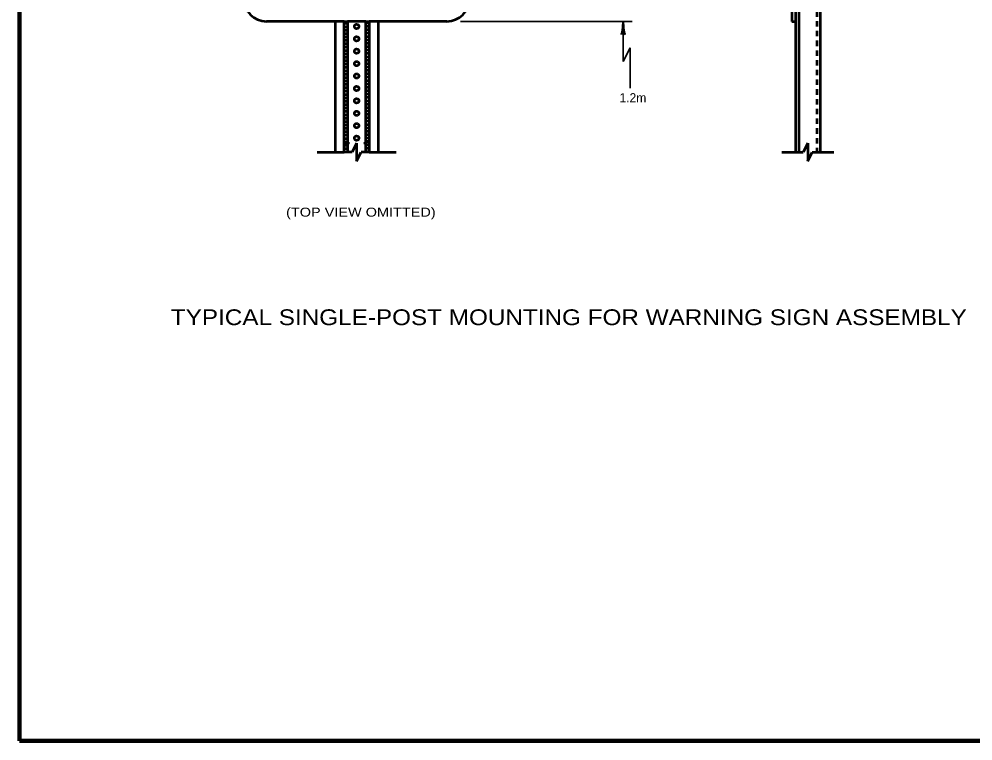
# Model space of a CAD drawing. Extents: x -87 to 768, y -466 to 78.
# Drawn here: x -29.9 to 223.8, y -454.3 to -262.3 of the extents above; entities that cross this region are included whole.
import ezdxf
from ezdxf.enums import TextEntityAlignment as Align

# ---------------------------------------------------------------- set-up
doc = ezdxf.new("R2010")
doc.units = 0
doc.header["$LTSCALE"] = 0.96
doc.header["$PDMODE"] = 32
doc.header["$PDSIZE"] = 0.48
doc.linetypes.add('SHORT_DASHED', pattern=[2.7, 1.5, -1.2])
doc.layers.add('1', color=7, linetype='Continuous', lineweight=53)

msp = doc.modelspace()

# ---------------------------------------------------------------- linework, layer by layer
at = {"layer": '1'}
for p, q in [((176.6102, -61.0329), (176.6102, -297.7179)), ((177.5102, -73.6329), (177.5102, -297.7179)), ((183.2102, -73.6329), (183.2102, -297.7179)), ((175.7102, -202.9179), (175.7102, -262.9179)), ((56.6102, -262.9179), (35.9102, -262.9179)), ((54.2102, -262.9179), (54.2102, -297.7179)), ((56.6102, -263.4375), (57.5102, -263.4375)), ((62.3102, -262.9179), (57.5102, -262.9179)), ((62.3102, -263.3133), (63.2102, -263.3133)), ((83.9102, -262.9179), (63.2102, -262.9179)), ((65.6102, -262.9179), (65.6102, -297.7179)), ((175.7102, -262.9179), (176.6102, -262.9179)), ((56.6102, -264.3375), (57.5102, -264.3375)), ((56.6102, -265.2375), (57.5102, -265.2375)), ((56.6102, -266.1375), (57.5102, -266.1375)), ((62.3102, -264.2133), (63.2102, -264.2133)), ((62.3102, -265.1133), (63.2102, -265.1133)), ((62.3102, -266.0133), (63.2102, -266.0133)), ((56.6102, -267.0375), (57.5102, -267.0375)), ((56.6102, -267.9375), (57.5102, -267.9375)), ((56.6102, -268.8375), (57.5102, -268.8375)), ((62.3102, -266.9133), (63.2102, -266.9133)), ((62.3102, -267.8133), (63.2102, -267.8133)), ((62.3102, -268.7133), (63.2102, -268.7133)), ((56.6102, -269.7375), (57.5102, -269.7375)), ((56.6102, -270.6375), (57.5102, -270.6375)), ((62.3102, -269.6133), (63.2102, -269.6133)), ((62.3102, -270.5133), (63.2102, -270.5133)), ((62.3102, -271.4133), (63.2102, -271.4133)), ((56.6102, -271.5375), (57.5102, -271.5375)), ((56.6102, -272.4375), (57.5102, -272.4375)), ((56.6102, -273.3375), (57.5102, -273.3375)), ((62.3102, -272.3133), (63.2102, -272.3133)), ((62.3102, -273.2133), (63.2102, -273.2133)), ((56.6102, -274.2375), (57.5102, -274.2375)), ((56.6102, -275.1375), (57.5102, -275.1375)), ((56.6102, -276.0375), (57.5102, -276.0375)), ((62.3102, -274.1133), (63.2102, -274.1133)), ((62.3102, -275.0133), (63.2102, -275.0133)), ((62.3102, -275.9133), (63.2102, -275.9133)), ((56.6102, -276.9375), (57.5102, -276.9375)), ((56.6102, -277.8375), (57.5102, -277.8375)), ((56.6102, -278.7375), (57.5102, -278.7375)), ((62.3102, -276.8133), (63.2102, -276.8133)), ((62.3102, -277.7133), (63.2102, -277.7133)), ((62.3102, -278.6133), (63.2102, -278.6133)), ((56.6102, -279.6375), (57.5102, -279.6375)), ((56.6102, -280.5375), (57.5102, -280.5375)), ((56.6102, -281.4375), (57.5102, -281.4375)), ((62.3102, -279.5133), (63.2102, -279.5133)), ((62.3102, -280.4133), (63.2102, -280.4133)), ((62.3102, -281.3133), (63.2102, -281.3133)), ((56.6102, -282.3375), (57.5102, -282.3375)), ((56.6102, -283.2375), (57.5102, -283.2375)), ((56.6102, -284.1375), (57.5102, -284.1375)), ((62.3102, -282.2133), (63.2102, -282.2133)), ((62.3102, -283.1133), (63.2102, -283.1133)), ((62.3102, -284.0133), (63.2102, -284.0133)), ((56.6102, -285.0375), (57.5102, -285.0375)), ((56.6102, -285.9375), (57.5102, -285.9375)), ((62.3102, -284.9133), (63.2102, -284.9133)), ((62.3102, -285.8133), (63.2102, -285.8133)), ((56.6102, -286.8375), (57.5102, -286.8375)), ((56.6102, -287.7375), (57.5102, -287.7375)), ((56.6102, -288.6375), (57.5102, -288.6375)), ((62.3102, -286.7133), (63.2102, -286.7133)), ((62.3102, -287.6133), (63.2102, -287.6133)), ((62.3102, -288.5133), (63.2102, -288.5133)), ((56.6102, -289.5375), (57.5102, -289.5375)), ((56.6102, -290.4375), (57.5102, -290.4375)), ((56.6102, -291.3375), (57.5102, -291.3375)), ((62.3102, -289.4133), (63.2102, -289.4133)), ((62.3102, -290.3133), (63.2102, -290.3133)), ((62.3102, -291.2133), (63.2102, -291.2133)), ((56.6102, -292.2375), (57.5102, -292.2375)), ((56.6102, -293.1375), (57.5102, -293.1375)), ((56.6102, -294.0375), (57.5102, -294.0375)), ((62.3102, -292.1133), (63.2102, -292.1133)), ((62.3102, -293.0133), (63.2102, -293.0133)), ((62.3102, -293.9133), (63.2102, -293.9133)), ((56.6102, -294.9375), (57.5102, -294.9375)), ((56.6102, -295.8375), (57.5102, -295.8375)), ((56.6102, -296.7375), (57.5102, -296.7375)), ((59.9102, -295.3179), (58.7102, -297.7179)), ((59.9102, -295.3179), (59.9102, -300.1179)), ((62.3102, -294.8133), (63.2102, -294.8133)), ((62.3102, -295.7133), (63.2102, -295.7133)), ((62.3102, -296.6133), (63.2102, -296.6133)), ((179.9102, -295.3179), (178.7102, -297.7179)), ((179.9102, -295.3179), (179.9102, -300.1179)), ((49.4102, -297.7179), (56.6102, -297.7179)), ((56.6102, -297.6375), (57.5102, -297.6375)), ((58.7102, -297.7179), (56.6102, -297.7179)), ((59.9102, -300.1179), (61.1102, -297.7179)), ((62.3102, -297.5133), (63.2102, -297.5133)), ((63.2102, -297.7179), (70.4102, -297.7179)), ((173.0102, -297.7179), (178.7102, -297.7179)), ((179.9102, -300.1179), (181.1102, -297.7179)), ((181.1102, -297.7179), (186.8102, -297.7179))]:
    msp.add_line(p, q, dxfattribs=at)
at = {"layer": '1', "linetype": 'SHORT_DASHED'}
msp.add_line((182.3102, -73.6329), (182.3102, -297.7179), dxfattribs=at)
at = {"layer": '1', "lineweight": 35}
for p, q in [((87.5102, -262.9179), (133.2183, -262.9179)), ((130.8183, -262.9179), (130.8183, -273.6154)), ((130.8183, -273.6154), (132.6557, -269.9635)), ((132.6557, -269.9635), (132.6557, -280.661))]:
    msp.add_line(p, q, dxfattribs=at)
at = {"layer": '1', "lineweight": 158}
msp.add_line((761.8126, -454.2894), (-29.7874, -454.2894), dxfattribs=at)
msp.add_lwpolyline([(761.8126, 71.8106), (-29.8874, 71.7106), (-29.7874, -454.2894)], dxfattribs=at)
at = {"layer": '1'}
for points in [[(56.6102, -297.7179), (56.6102, -262.9179), (57.5102, -262.9179), (57.5102, -297.7179)], [(62.3102, -297.7179), (62.3102, -262.9179), (63.2102, -262.9179), (63.2102, -297.7179), (61.1102, -297.7179)]]:
    msp.add_lwpolyline(points, dxfattribs=at)
for centre in [(59.9102, -264.2643), (59.9102, -267.5643), (59.9102, -270.8643), (59.9102, -274.1643), (59.9102, -277.4643), (59.9102, -280.7643), (59.9102, -284.0643), (59.9102, -287.3643), (59.9102, -290.6643), (59.9102, -293.9643)]:
    msp.add_circle(centre, 0.6, dxfattribs=at)
for centre, start, end in [((35.9102, -256.9179), 180, 270), ((83.9102, -256.9179), 270, 0)]:
    msp.add_arc(centre, 6, start, end, dxfattribs=at)
at = {"layer": '1', "lineweight": 40}
for centre, major_axis, ratio, start_param, end_param in [((130.5644, -264.2625), (0.2108, 2.1077), 0.07063, 3.14071475, 5.41810995), ((131.1499, -264.2273), (-0.1874, 2.1428), 0.122415, 0.89635335, 3.14159265)]:
    msp.add_ellipse(centre, major_axis=major_axis, ratio=ratio, start_param=start_param, end_param=end_param, dxfattribs=at)
at = {"layer": '1'}
for p in [(57.5102, -295.3179), (62.3102, -295.3179)]:
    msp.add_point(p, dxfattribs=at)

# ---------------------------------------------------------------- texts
msp.add_text('1.2m', height=2.4, dxfattribs=at).set_placement((133.3929, -284.427), align=Align.CENTER)
for s, height, width, p in [('(TOP VIEW OMITTED)', 2.4, 1.2, (61.0326, -314.8582)), ('TYPICAL SINGLE-POST MOUNTING FOR WARNING SIGN ASSEMBLY', 4.2, 1.15, (116.3441, -343.7086))]:
    msp.add_text(s, height=height, dxfattribs=dict(at, width=width)).set_placement(p, align=Align.CENTER)

doc.saveas('drawing.dxf')
